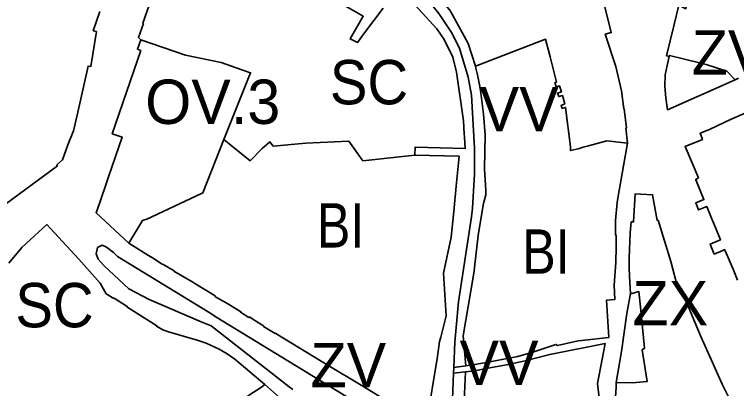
# Model space of a CAD drawing. Extents: x -650451 to -642268, y -1075216 to -1066610.
# Drawn here: x -647170.1 to -646925.8, y -1070898.5 to -1070772 of the extents above; entities that cross this region are included whole.
import ezdxf

# ---------------------------------------------------------------- set-up
doc = ezdxf.new("R2010")
doc.units = 0
doc.header["$LTSCALE"] = 6
doc.layers.add('1', color=7, linetype='Continuous', lineweight=35)
doc.layers.add('2', color=7, linetype='Continuous')

msp = doc.modelspace()

# ---------------------------------------------------------------- linework, layer by layer
at = {"layer": '1'}
msp.add_line((-647017.4, -1070890.8), (-647021.458, -1070891.298), dxfattribs=at)
for points in [[(-646948.64, -1070786.2), (-646949.48, -1070785.99), (-646947.09, -1070775.88), (-646945.36, -1070768.9), (-646942.95, -1070770.09), (-646942.5, -1070768.36), (-646933.96, -1070735.12), (-646933.16, -1070732.02), (-646932, -1070732.32), (-646921.48, -1070735.03)], [(-647116.63, -1070746.3), (-647126.7, -1070775.01), (-647126.45, -1070775.1), (-647128.13, -1070779.81), (-647127.36, -1070780.55)], [(-647037.47, -1070750.49), (-647039.47, -1070754.14), (-647039.84, -1070754.92), (-647040.16, -1070755.74), (-647036.53, -1070759.54), (-647034.6, -1070761.61), (-647026.48, -1070771.66), (-647022.25, -1070778.15), (-647019.56, -1070783.47), (-647016.65, -1070793.24), (-647015.43, -1070799.33), (-647014.49, -1070817.24), (-647014.48, -1070825.99), (-647015.09, -1070837.53), (-647015.44, -1070840.42), (-647019.93, -1070869.12), (-647021.12, -1070882.75), (-647021.458, -1070891.298)], [(-647014.17, -1070789.53), (-647016.59, -1070781.8), (-647021.95, -1070772.16), (-647022.81, -1070770.62), (-647025.79, -1070767.12), (-647037.47, -1070750.49)], [(-647034.61, -1070819.54), (-647034.58, -1070816.84), (-647017.62, -1070817.34), (-647017.85, -1070813.46), (-647017.91, -1070812.41), (-647018.2, -1070808.02), (-647020.59, -1070791.49), (-647021.84, -1070786.49), (-647024.74, -1070780.46), (-647027.19, -1070776.89), (-647029.79, -1070774.04), (-647030.78, -1070772.96), (-647039.58, -1070763.3)], [(-647045.34, -1070769.89), (-647051.64, -1070778.2), (-647053.99, -1070781.45), (-647056.58, -1070780.29), (-647052.1, -1070772.65), (-647063.21, -1070766.15)], [(-646970.32, -1070769.4), (-646968.19, -1070778.16), (-646970.21, -1070778.7), (-646966.6, -1070789.62), (-646964.71, -1070797.83), (-646963.99, -1070803.89), (-646963.84, -1070803.87), (-646963.1, -1070810.38), (-646963.26, -1070810.4), (-646962.68, -1070815.49)], [(-647175.38, -1070837.69), (-647155.58, -1070823.14), (-647155.75, -1070822.9), (-647153.79, -1070821.2), (-647152.04, -1070816.1), (-647150.11, -1070811.41), (-647148.93, -1070806.11), (-647145.2, -1070789.46), (-647144.22, -1070789.61), (-647142.36, -1070777.81), (-647143.41, -1070777.52), (-647141.17, -1070771.01)], [(-647127.36, -1070780.55), (-647128.47, -1070783.81), (-647127.34, -1070784.21), (-647137.02, -1070812.37), (-647133.65, -1070813.55), (-647138.27, -1070826.9), (-647138.87, -1070828.63), (-647141.13, -1070835.25), (-647142.47, -1070839.07), (-647131.43, -1070849.34)], [(-647127.36, -1070780.55), (-647112.25, -1070785.78), (-647100.16, -1070788.3), (-647093.12, -1070790.76), (-647090.24, -1070791.73), (-647099.26, -1070814.25)], [(-646962.68, -1070815.49), (-646969.72, -1070814.79), (-646975.86, -1070816.38), (-646977.76, -1070816.93), (-646979.37, -1070817.4), (-646981.97, -1070818.04), (-646981.97, -1070816.79), (-646983.68, -1070803.47), (-646984.76, -1070803.79), (-646985.16, -1070802.75), (-646983.95, -1070802.22), (-646984.72, -1070799.46), (-646985.97, -1070799.81), (-646986.4, -1070798.61), (-646985.07, -1070798.18), (-646985.73, -1070796.18), (-646986.88, -1070796.5), (-646987.28, -1070795.05), (-646986.7, -1070794.86), (-646988.91, -1070786.4), (-646990.47, -1070780.4), (-647014.17, -1070789.53)], [(-646948.64, -1070786.2), (-646949.3, -1070789.28), (-646949.97, -1070792.46), (-646950.1, -1070796.26), (-646949.73, -1070800.24), (-646949.18, -1070804.22), (-646926.29, -1070794.08)], [(-646948.64, -1070786.2), (-646948.55, -1070785.86), (-646938.33, -1070788.42), (-646936.1, -1070788.99), (-646929.07, -1070791.17), (-646926.29, -1070794.08)], [(-647017.4, -1070890.8), (-647018.3, -1070880.69), (-647015.68, -1070865.44), (-647014.63, -1070858.82), (-647014.43, -1070857.54), (-647013.26, -1070846.7), (-647012.31, -1070841.21), (-647011.39, -1070835.93), (-647010.59, -1070832.94), (-647010.68, -1070831.5), (-647011.11, -1070824.16), (-647010.89, -1070812.67), (-647011.38, -1070805.72), (-647012.34, -1070798.51), (-647012.66, -1070796.33), (-647013.41, -1070792.39), (-647013.97, -1070790.15), (-647014.17, -1070789.53)], [(-646925.14, -1070793.57), (-646926.29, -1070794.08)], [(-646920.6, -1070804.42), (-646927.81, -1070807.55), (-646934.79, -1070810.78), (-646937.8, -1070812.01), (-646938.18, -1070812.2), (-646937.34, -1070814.25), (-646943.25, -1070816.65), (-646938.71, -1070827.23), (-646939.64, -1070827.79), (-646939.58, -1070827.93), (-646938.33, -1070831), (-646936.86, -1070834.57), (-646939.64, -1070835.71), (-646938.71, -1070838.08), (-646935.9, -1070836.93), (-646934.07, -1070841.39), (-646934.02, -1070841.52), (-646933.96, -1070841.66), (-646932.72, -1070844.62), (-646931.22, -1070848.17), (-646931.81, -1070848.41), (-646934.73, -1070849.64), (-646933.37, -1070853.01), (-646930.42, -1070851.77), (-646929.81, -1070851.51), (-646929.64, -1070851.92), (-646928.35, -1070854.99), (-646928.22, -1070855.29), (-646927.01, -1070858.15), (-646925.45, -1070861.82)], [(-647131.43, -1070849.34), (-647126.83, -1070841.67), (-647125.33, -1070841.27), (-647106.77, -1070832.55), (-647106.33, -1070832.34), (-647099.26, -1070814.25)], [(-647034.61, -1070819.54), (-647052.19, -1070821.53), (-647056.92, -1070814.86), (-647071.51, -1070815.52), (-647082.58, -1070816.51), (-647083.69, -1070815.12), (-647086.31, -1070817.34), (-647090.38, -1070821.49), (-647099.26, -1070814.25)], [(-646962.68, -1070815.49), (-646965.82, -1070833.4), (-646966.22, -1070835.58), (-646966.77, -1070841.69), (-646966.82, -1070844.53), (-646966.78, -1070846.31), (-646966.59, -1070846.94), (-646966.54, -1070847.91), (-646966.5, -1070850.6), (-646966.68, -1070855.86), (-646967.22, -1070863.48), (-646967, -1070868.38), (-646969.81, -1070868.59), (-646969.05, -1070881.19), (-646970.16, -1070881.34), (-646976.1, -1070882), (-646979.35, -1070882.38), (-646986.44, -1070883.9), (-646986.9, -1070883.55), (-646994.09, -1070885.91), (-646995.53, -1070886.37), (-646999.84, -1070887.67), (-647003.4, -1070888.32), (-647009.89, -1070889.52), (-647014.35, -1070890.34), (-647017.4, -1070890.8)], [(-647034.61, -1070819.54), (-647019.67, -1070819.93), (-647020.65, -1070830.04), (-647021.49, -1070838.65), (-647022.34, -1070847.31), (-647024.94, -1070859.43), (-647024.1, -1070873.9), (-647025.88, -1070881.07), (-647026.25, -1070882.53), (-647027.05, -1070888.44), (-647027.85, -1070893.09), (-647029.81, -1070904.76)], [(-646961.64, -1070866.39), (-646961.98, -1070860.56), (-646962.14, -1070857.56), (-646962.14, -1070857.11), (-646962.18, -1070855.82), (-646962.19, -1070854.43), (-646961.83, -1070845.86), (-646961.46, -1070842.07), (-646960.63, -1070842.14), (-646960.12, -1070832.69), (-646954.22, -1070832.97), (-646952.63, -1070841.63), (-646952.34, -1070841.59), (-646948.05, -1070855.57), (-646945.42, -1070865.4), (-646944.54, -1070865), (-646937.85, -1070880.9), (-646934, -1070889.69), (-646930.63, -1070896.98), (-646927.58, -1070903.24)], [(-647085.4, -1070897.14), (-647095.52, -1070888.57), (-647098.18, -1070886.71), (-647100.79, -1070885.17), (-647105.19, -1070883.09), (-647108.31, -1070882.14), (-647117.94, -1070879.25), (-647119.85, -1070878.57), (-647122, -1070877.41), (-647121.89, -1070877.25), (-647129.57, -1070872.37), (-647132.03, -1070870.82), (-647131.98, -1070870.73), (-647136.41, -1070867.92), (-647136.47, -1070868), (-647139.02, -1070866.44), (-647141.09, -1070862.83), (-647148.3, -1070854.79), (-647157.95, -1070844.35), (-647159.11, -1070843.05), (-647167.65, -1070850.81), (-647171.97, -1070856.04)], [(-647075.9, -1070898.84), (-647077.16, -1070897.85), (-647103.57, -1070877.32), (-647106.9, -1070875.89), (-647124.51, -1070868.42), (-647131.43, -1070864.72), (-647139.73, -1070857.02), (-647141.78, -1070854.71), (-647142.49, -1070852.95), (-647142.02, -1070850.81), (-647140.46, -1070849.98), (-647138.98, -1070850.63), (-647136.62, -1070852.49), (-647135.27, -1070853.78), (-647104.58, -1070872.51), (-647101.59, -1070874.43), (-647072.94, -1070891.9), (-647071.49, -1070892.79), (-647041.52, -1070911.06)], [(-647035.98, -1070907.53), (-647052.83, -1070897.35), (-647063.75, -1070890.75), (-647074.06, -1070884.49), (-647081.35, -1070880.06), (-647081.84, -1070879.77), (-647081.89, -1070879.84), (-647085.79, -1070877.49), (-647085.74, -1070877.4), (-647086.39, -1070876.9), (-647090.69, -1070874.28), (-647090.78, -1070874.43), (-647093.57, -1070872.69), (-647093.48, -1070872.53), (-647097.73, -1070869.9), (-647102.27, -1070867.33), (-647102.16, -1070867.16), (-647109.06, -1070862.97), (-647109.74, -1070862.55), (-647113.19, -1070860.43), (-647113.25, -1070860.52), (-647116.16, -1070858.77), (-647116.09, -1070858.66), (-647119.55, -1070856.6), (-647119.59, -1070856.68), (-647120.31, -1070856.28), (-647123.82, -1070853.99), (-647123.88, -1070854.09), (-647131.43, -1070849.34)], [(-646966.49, -1070896.41), (-646960.96, -1070896.52), (-646956.11, -1070896.11), (-646957.76, -1070885.38), (-646956.95, -1070884.83), (-646958.26, -1070870.84), (-646958.86, -1070865.71), (-646961.14, -1070866.33), (-646961.64, -1070866.39)], [(-646961.64, -1070866.39), (-646962.93, -1070873.05), (-646964.71, -1070885.94), (-646966.49, -1070896.41)], [(-647017.56, -1070892.83), (-647014.34, -1070892.43), (-647009.97, -1070891.58), (-647003.61, -1070890.44), (-646997.35, -1070889.14), (-646989.03, -1070886.94), (-646970.21, -1070883.28), (-646972.8, -1070896.79), (-646971.53, -1070908.18)], [(-647017.56, -1070892.83), (-647021.538, -1070893.318), (-647021.458, -1070891.298)], [(-647017.56, -1070892.83), (-647018, -1070902.77), (-647017.58, -1070909.54)], [(-647017.58, -1070909.54), (-647020.36, -1070910.04), (-647020.92, -1070910.05), (-647021.32, -1070910.06), (-647021.68, -1070908.46), (-647022, -1070905.02), (-647021.538, -1070893.318)], [(-647085.4, -1070897.14), (-647086.47, -1070898), (-647090.87, -1070900.84), (-647091.46, -1070901.32), (-647098.82, -1070905.97), (-647110.92, -1070913.23)], [(-647085.4, -1070897.14), (-647080.53, -1070901.41), (-647078.43, -1070903.2), (-647069.27, -1070911.03), (-647063.93, -1070915.6), (-647062.93, -1070916.46), (-647062.48, -1070916.84), (-647055.69, -1070922.66), (-647052.6, -1070925.35), (-647048.23, -1070929.16), (-647041.01, -1070942.31), (-647040.4, -1070946.32)], [(-646964.86, -1070934.1), (-646966.05, -1070927.3), (-646967.16, -1070921.01), (-646967.33, -1070913.32), (-646967.09, -1070905.57), (-646966.97, -1070904.74), (-646966.59, -1070898), (-646966.49, -1070896.41)]]:
    msp.add_lwpolyline(points, dxfattribs=at)

# ---------------------------------------------------------------- texts
at = {"layer": '2'}
for s, p in [('ZV', (-646941.009, -1070792.359)), ('OV.3', (-647125.87, -1070809.04)), ('VV', (-647012.724, -1070811.522)), ('ZX', (-646961.03, -1070877.12)), ('ZV', (-647069.954, -1070898.023)), ('VV', (-647019.531, -1070897.233))]:
    msp.add_text(s, height=15, dxfattribs=at).set_placement(p)
for s, width, p in [('SC', 0.95, (-647063.389, -1070802.411)), ('BI', 0.85, (-647067.823, -1070850.808)), ('BI', 0.85, (-646998.367, -1070859.675)), ('SC', 0.95, (-647169.79, -1070877.777))]:
    msp.add_text(s, height=15, dxfattribs=dict(at, width=width)).set_placement(p)

doc.saveas('drawing.dxf')
